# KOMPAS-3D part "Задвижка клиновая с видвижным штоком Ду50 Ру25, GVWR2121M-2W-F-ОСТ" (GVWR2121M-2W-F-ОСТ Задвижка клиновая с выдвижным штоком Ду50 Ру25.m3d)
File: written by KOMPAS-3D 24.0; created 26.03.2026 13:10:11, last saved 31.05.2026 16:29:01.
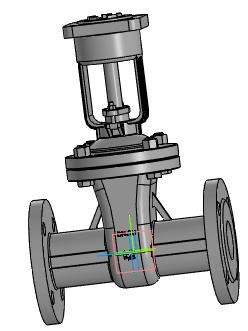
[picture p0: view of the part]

Document properties: Автор: R2D2; Полное имя файла: E:\Работа\Зайцев\GVWR2121M-2W-F-ОСТ Задвижка клиновая 30с964нж DN.ru Ду50-300 Ру25\исходные материалы\DN50\GVWR2121M-2W-F-ОСТ Задвижка клиновая с видвижным штоком Ду50 Ру25.m3d

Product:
- Component [detail]: AS 1110 - M12 x 45  | qty 4  | pos. 2  | Комментарий: Болты и винты   шестигранные точные   метрические ISO; Автор: R2D2; additional columns: Сталь, мягкая; source file: AS 1110 - M12 x 45 AS 1110 - M12 x 45.m3d
- Component [detail]: ANSI B18.2.4.2M - M12x1,75 - 18  | designation ANSI B18.2.4.2M - M12x1,75  | qty 4  | pos. 3  | Комментарий: Типы метрических   шестигранных гаек   2; Автор: R2D2; additional columns: Сталь, мягкая; source file: ANSI B18.2.4.2M - M12x1,75 ANSI B18.2.4.2M - M12x1,75 - 18.m3d
- Component [detail]: ANSI B18.2.4.2M - M5x0,8 - 8  | designation ANSI B18.2.4.2M - M5x0,8  | qty 1  | pos. 4  | Комментарий: Типы метрических   шестигранных гаек   2; Автор: R2D2; additional columns: Сталь, мягкая; source file: ANSI B18.2.4.2M - M5x0,8 ANSI B18.2.4.2M - M5x0,8 - 8.m3d
- Component [detail]: Деталь1  | qty 1  | pos. 5  | Автор: R2D2; additional columns: Типовые; source file: 2.m3d
- Component [detail]: Фланец  | qty 1  | pos. 5  | Автор: R2D2; additional columns: Типовые; source file: Фланец DN50 PN25 D160 b18.m3d
- Component [detail]: Фланец  | designation 01  | qty 1  | pos. 6  | Автор: R2D2; additional columns: Типовые; source file: Фланец DN50 PN25 D160 b18.m3d
- Component [detail]: ANSI B18.2.4.2M - M5x0,8 - 8  | designation ANSI B18.2.4.2M - M5x0,8-01  | qty 1  | pos. 7  | Комментарий: Типы метрических   шестигранных гаек   2; Автор: R2D2; additional columns: Сталь, мягкая; source file: ANSI B18.2.4.2M - M5x0,8 ANSI B18.2.4.2M - M5x0,8 - 8.m3d
- Component [assembly]: DN50_3D_STEP  | designation Сборка  | qty 1  | Масса: 2.725126; Автор: R2D2; source file: Фланец А.a3d
- Body: Тело 1  | qty 1
    Масса: 21.562222
- Part/product: Задвижка клиновая с видвижным штоком Ду50 Ру25  | designation GVWR2121M-2W-F-ОСТ
    Масса: 17
    Раздел спецификации: Прочие изделия
    Примечание: D040-09833

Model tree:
1. Массив по концентрической сетке:1  (labels: Грань.Твердое тело1)  (4 pattern instances)
     Шаг 2 = 360
2. Скругление:1  (with: Ребро.Операция без истории:2)
     Радиус = 5
3. Элемент выдавливания:1  (with: Грань.Элемент выдавливания:1, Грань.Операция без истории:2)
     Расстояние 1 = 48.9137
4. Элемент выдавливания:2  (with: Грань.Элемент выдавливания:1)
     Расстояние 1 = 65.9137; Смещение 1 = 55
5. Элемент выдавливания:3  (with: Грань.Элемент выдавливания:1, Грань.Элемент вращения:1)
     Расстояние 1 = 44.6136
6. Элемент выдавливания:4  (with: Грань.Элемент выдавливания:1, Грань.Элемент вращения:1)
     Расстояние 1 = 42.9933
7. Скругление:2  (with: Ребро.Элемент выдавливания:3, Ребро.Элемент выдавливания:4)
     Радиус = 2
8. Эскиз:1
9. Элемент выдавливания:5  (with: Грань.Элемент выдавливания:1, Грань.Элемент вращения:1, Грань.Операция без истории:2)  (labels: Грань.Твердое тело1; Грань.Solid1; Solid1; Твердое тело1)
     Расстояние 1 = 46; Смещение 1 = 1; Расстояние = -125; Ориентация = 2; Ориентация = 2; Расстояние = -305

Referenced files in E:\Работа\Зайцев\GVWR2121M-2W-F-ОСТ Задвижка клиновая 30с964нж DN.ru Ду50-300 Ру25\исходные материалы\DN50\: AS 1110 - M12 x 45 AS 1110 - M12 x 45.m3d, ANSI B18.2.4.2M - M12x1,75 ANSI B18.2.4.2M - M12x1,75 - 18.m3d, ANSI B18.2.4.2M - M5x0,8 ANSI B18.2.4.2M - M5x0,8 - 8.m3d, 2.m3d, Фланец А.a3d, Фланец DN50 PN25 D160 b18.m3d
Referenced files in E:\Работа\Зайцев\GVWR3131M-2W-F-S Задвижка клиновая с выдвижным штоком DN.ru Ду50-200 Ру63\DN50\исходные материалы\: ANSI B18.2.4.2M - M12x1,75 ANSI B18.2.4.2M - M12x1,75 - 18.m3d, AS 1110 - M12 x 45 AS 1110 - M12 x 45.m3d
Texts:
  GVWR2121M-2W-F-ОСТ
  Ду50
  GOST 26.020 Pr3
  Ру25
  AS 1110 - M12 x 45 AS 1110 - M12 x 45 (1)
  ANSI B18.2.4.2M - M12x1,75 ANSI B18.2.4.2M - M12x1,75 - 18 (1)
  ANSI B18.2.4.2M - M5x0,8 ANSI B18.2.4.2M - M5x0,8 - 8
  Деталь1 Деталь1
  ANSI B18.2.4.2M - M12x1,75 ANSI B18.2.4.2M - M12x1,75 - 18 (2)
  AS 1110 - M12 x 45 AS 1110 - M12 x 45 (2)
  ANSI B18.2.4.2M - M12x1,75 ANSI B18.2.4.2M - M12x1,75 - 18 (3)
  AS 1110 - M12 x 45 AS 1110 - M12 x 45 (3)
  ANSI B18.2.4.2M - M12x1,75 ANSI B18.2.4.2M - M12x1,75 - 18 (4)
  AS 1110 - M12 x 45 AS 1110 - M12 x 45 (4)
  ANSI B18.2.4.2M - M5x0,8-01 ANSI B18.2.4.2M - M5x0,8 - 8
  Сборка DN50_3D_STEP
  Ось Y.Начало координат
  Ось Z.Начало координат
  Плоскость ZX.Начало координат
  Плоскость XY.Начало координат
  Плоскость ZY.Начало координат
